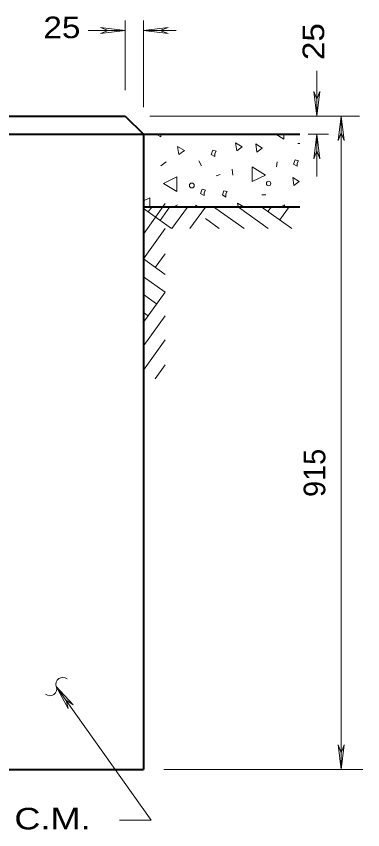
# Model space of a CAD drawing. Extents: x 312583 to 312854, y 144419 to 144597.
# Drawn here: x 312790.2 to 312802.38, y 144440.37 to 144469 of the extents above; entities that cross this region are included whole.
import ezdxf

# ---------------------------------------------------------------- set-up
doc = ezdxf.new("R2010")
doc.units = 0
doc.header["$LTSCALE"] = 0.3
doc.layers.add('1', color=7, linetype='Continuous', lineweight=25)
doc.layers.add('2', color=7, linetype='Continuous', lineweight=13)

msp = doc.modelspace()

# ---------------------------------------------------------------- linework, layer by layer
at = {"layer": '1', "lineweight": 40}
for p, q in [((312728.8566, 144465.4868), (312794.0232, 144465.4868)), ((312794.0232, 144465.4868), (312794.6672, 144464.8505)), ((312788.2272, 144464.8505), (312800.1719, 144464.8505)), ((312794.6672, 144464.8505), (312794.6672, 144442.4868)), ((312794.6672, 144462.2898), (312800.1719, 144462.2898)), ((312728.2202, 144442.4868), (312794.6672, 144442.4868))]:
    msp.add_line(p, q, dxfattribs=at)
at = {"layer": '2'}
for p, q in [((312794.0232, 144466.3915), (312794.0232, 144468.8448)), ((312794.6672, 144465.8011), (312794.6672, 144468.8448)), ((312792.7199, 144468.4998), (312794.0232, 144468.4998)), ((312793.1569, 144468.6071), (312793.4329, 144468.4998)), ((312794.0232, 144468.4998), (312793.1569, 144468.6071)), ((312793.1569, 144468.3925), (312793.4329, 144468.4998)), ((312794.0232, 144468.4998), (312793.1569, 144468.3925)), ((312794.6672, 144468.4998), (312795.5336, 144468.6071)), ((312794.6672, 144468.4998), (312795.8172, 144468.4998)), ((312794.6672, 144468.4998), (312795.5336, 144468.3925)), ((312795.5336, 144468.6071), (312795.2576, 144468.4998)), ((312795.5336, 144468.3925), (312795.2576, 144468.4998)), ((312800.7664, 144465.4868), (312800.7664, 144467.0738)), ((312800.659, 144466.3531), (312800.7664, 144466.0771)), ((312800.7664, 144465.4868), (312800.659, 144466.3531)), ((312800.8737, 144466.3531), (312800.7664, 144466.0771)), ((312800.7664, 144465.4868), (312800.8737, 144466.3531)), ((312794.8896, 144465.4868), (312802.2669, 144465.4868)), ((312801.6223, 144465.4868), (312801.515, 144464.6205)), ((312801.6223, 144442.4868), (312801.6223, 144465.4868)), ((312801.6223, 144465.4868), (312801.7297, 144464.6205)), ((312799.3209, 144464.8505), (312799.6046, 144464.6741)), ((312799.6046, 144464.6741), (312799.6046, 144464.8505)), ((312800.4615, 144464.8505), (312801.1713, 144464.8505)), ((312800.7664, 144464.8505), (312800.659, 144463.9841)), ((312800.7664, 144463.3631), (312800.7664, 144464.8505)), ((312800.7664, 144464.8505), (312800.8737, 144463.9841)), ((312801.515, 144464.6205), (312801.6223, 144464.8965)), ((312801.7297, 144464.6205), (312801.6223, 144464.8965)), ((312794.6672, 144464.6051), (312794.6979, 144464.5975)), ((312800.1029, 144464.5208), (312800.1719, 144464.5208)), ((312800.659, 144463.9841), (312800.7664, 144464.2601)), ((312800.8737, 144463.9841), (312800.7664, 144464.2601)), ((312795.4646, 144463.8691), (312795.2806, 144463.7311)), ((312796.6146, 144463.9075), (312796.7066, 144463.7388)), ((312799.3439, 144463.6928), (312799.3669, 144463.8768)), ((312797.7876, 144463.6161), (312797.8106, 144463.4015)), ((312797.2202, 144463.3785), (312797.3659, 144463.4245)), ((312798.8302, 144462.7115), (312798.9759, 144462.7115)), ((312795.4262, 144462.4048), (312794.6672, 144461.3315)), ((312795.6562, 144461.5308), (312794.6672, 144462.2361)), ((312794.9586, 144462.2821), (312794.8359, 144462.1135)), ((312795.5872, 144462.2821), (312795.2576, 144461.8145)), ((312796.2159, 144462.2821), (312795.6716, 144461.5231)), ((312795.7406, 144462.2898), (312795.8632, 144462.3588)), ((312796.8446, 144462.2821), (312796.3002, 144461.5231)), ((312798.2092, 144461.5308), (312797.1359, 144462.2898)), ((312799.0526, 144461.5308), (312798.0099, 144462.2745)), ((312799.8806, 144461.5308), (312798.7919, 144462.3051)), ((312799.1676, 144462.2898), (312799.0449, 144462.1211)), ((312799.7962, 144462.2898), (312799.4666, 144461.8298)), ((312797.3276, 144461.5308), (312796.8446, 144461.8758)), ((312795.4262, 144461.5231), (312794.6672, 144460.4575)), ((312794.6672, 144460.4575), (312795.4262, 144459.9131)), ((312795.4262, 144460.6415), (312795.0812, 144460.1585)), ((312794.6672, 144459.8288), (312795.4262, 144459.2845)), ((312795.4262, 144459.2845), (312794.6519, 144458.1958)), ((312794.6672, 144459.2001), (312795.1272, 144458.8705)), ((312794.6672, 144458.5715), (312794.8359, 144458.4488)), ((312795.4262, 144458.4488), (312794.6826, 144457.4138)), ((312795.4262, 144457.6131), (312794.6672, 144456.5398)), ((312795.4262, 144456.7315), (312795.0812, 144456.2408)), ((312791.6006, 144445.4078), (312792.0146, 144444.6335)), ((312791.6006, 144445.4078), (312792.1909, 144444.7638)), ((312792.0146, 144444.6335), (312791.9456, 144444.9248)), ((312792.1909, 144444.7638), (312791.9456, 144444.9248)), ((312801.515, 144443.3531), (312801.6223, 144443.0771)), ((312801.6223, 144442.4868), (312801.515, 144443.3531)), ((312801.7297, 144443.3531), (312801.6223, 144443.0771)), ((312801.6223, 144442.4868), (312801.7297, 144443.3531)), ((312795.3802, 144442.4868), (312802.379, 144442.4868))]:
    msp.add_line(p, q, dxfattribs=at)
for points in [[(312795.1579, 144464.8505), (312795.1502, 144464.8275), (312795.2806, 144464.7508), (312795.2806, 144464.8505)], [(312794.8896, 144462.2898), (312794.8896, 144462.6118), (312794.6672, 144462.4968)], [(312796.5916, 144462.2975), (312796.5072, 144462.3435), (312796.5149, 144462.2898)], [(312798.2016, 144462.2898), (312797.9792, 144462.4201), (312798.0022, 144462.2975)], [(312799.6276, 144462.2898), (312799.6276, 144462.3588), (312799.5049, 144462.2898)], [(312793.8239, 144440.7081), (312794.9356, 144440.7081), (312791.6006, 144445.4078)]]:
    msp.add_lwpolyline(points, dxfattribs=at)
for points in [[(312797.9486, 144464.2601), (312798.1402, 144464.4058), (312797.9102, 144464.5438)], [(312798.6539, 144464.2141), (312798.8456, 144464.3598), (312798.6156, 144464.5055)], [(312795.9169, 144464.1298), (312796.1086, 144464.2755), (312795.8709, 144464.4135)], [(312797.1819, 144464.1681), (312797.2279, 144464.2525), (312797.1129, 144464.2831), (312797.0516, 144464.1375), (312797.1819, 144464.0608)], [(312800.0722, 144463.8231), (312800.1182, 144463.9075), (312800.0032, 144463.9458), (312799.9496, 144463.7925), (312800.0722, 144463.7235)], [(312798.4929, 144463.6928), (312798.4929, 144463.1791), (312798.9606, 144463.4091)], [(312795.8402, 144462.8341), (312795.8402, 144463.3478), (312795.3726, 144463.1101)], [(312799.9572, 144463.0411), (312800.1489, 144463.1868), (312799.9189, 144463.3248)], [(312796.7986, 144462.7958), (312796.8522, 144462.8801), (312796.7296, 144462.9108), (312796.6759, 144462.7575), (312796.7986, 144462.6885)], [(312797.5652, 144462.7421), (312797.6112, 144462.8265), (312797.4962, 144462.8571), (312797.4426, 144462.7115), (312797.5652, 144462.6348)]]:
    msp.add_lwpolyline(points, close=True, dxfattribs=at)
for centre, radius in [((312796.3697, 144463.0409), 0.0865), ((312799.0695, 144463.1113), 0.0784)]:
    msp.add_circle(centre, radius, dxfattribs=at)
for centre, start, end in [((312791.8283, 144445.4886), 50.36848, 200.36848), ((312791.3792, 144445.3219), 230.36848, 20.36848)]:
    msp.add_arc(centre, 0.2395, start, end, dxfattribs=at)

# ---------------------------------------------------------------- texts
for s, width, p in [('25 ', 1.15, (312791.1506, 144468.2259)), ('APPROX.  1.5 C.M.', 1.25, (312781.6558, 144440.3775))]:
    msp.add_text(s, height=0.76, dxfattribs=dict(at, width=width)).set_placement(p)
at = {"layer": '2', "width": 1.15}
msp.add_text('25 ', height=0.76, rotation=90, dxfattribs=at).set_placement((312801.0244, 144467.4552))
at = {"layer": '2'}
msp.add_text('915', height=0.76, rotation=90, dxfattribs=at).set_placement((312801.0631, 144452.0779))

doc.saveas('drawing.dxf')
